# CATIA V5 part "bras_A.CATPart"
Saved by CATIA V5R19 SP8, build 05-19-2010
Part number: bras_A
Bounding box of the stored display mesh (mm): x -17.5 to 17.5, y -17.5 to 20.5, z 0 to 317.322
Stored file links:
  G:\EU_thinkMotion\CFAO_2010\MMS_groupe3\MMS_groupe3\A reprendre\mmugnier\Systeme_Cric_Y\Systeme_Cric_Y\bras_A.CATPart
  C:\Users\matthieu\Desktop\CFAO\Systeme_Cric_Y\Cric_Y.CATProduct
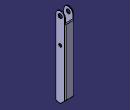
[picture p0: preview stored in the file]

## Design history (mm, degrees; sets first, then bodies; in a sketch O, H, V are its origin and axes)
Set1
  Plane1 "Plan de symétrie": linked copy from another document
  Plane2 "Plan exter bas": linked copy from another document
  Plane3: linked copy from another document
  Plane4 "Plan inter bas": linked copy from another document
  Line1 "Axe 3": linked copy from another document
  Plane5: linked copy from another document
  Plane6 "Plan exter droit": linked copy from another document
  Plane7 "Plan exter gauche": linked copy from another document
  Line2 "Axe 2": linked copy from another document
Body1 (main body)
  Sketch1 on Plane1, origin (0, 0, 0), H (0, 1, 0), V (0, 0, 1)
    line L1 (0, 0) -> (20.5, 20.5)
    line L2 (20.5, 20.5) -> (20.5, 279.5)
    line L3 (20.5, 279.5) -> (17.5, 282.5)
    line L4 (17.5, 282.5) -> (17.5, 300)
    arc A1 centre (0, 300) radius 17.5 from (17.5, 300) to (-17.5, 300) ccw
    point P5 (0, 300)
    line L5 (-17.5, 300) -> (-17.5, 4.6891)
    line L6 (-17.5, 4.6891) -> (0, 0)
    reference intersected line E1 through (20.5, 0) direction (0, 1) from Plane2
    reference intersected line E2 through (-17.5, 0) direction (0, 1) from Plane3
    reference intersected line E3 through (17.5, 0) direction (0, 1) from Plane4
    reference projected point E4 (0, 300) from Line1
    reference projected point E5 (0, 300) from Line1
    angle L3 L4 = 45
    angle L1 L6 = 120
    angle L1 L2 = 135
    vertical: L2 V, L4 V
    tangency: A1 L4, L5 A1
    coincidence: L2 E1, E2 L5, E3 L4, L3 E4, P5 E5
  Sketch2 on Plane5, origin (0, 0, 0), H (1, 0, 0), V (0, 1, 0)
    line L1 (-17.5, -17.5) -> (-14.5, -17.5)
    line L2 (17.5, -17.5) -> (17.5, 17.5)
    arc A1 centre (14.5, 17.5) radius 3 from (17.5, 17.5) to (14.5, 20.5) ccw
    line L3 (14.5, 20.5) -> (-14.5, 20.5)
    arc A2 centre (-14.5, 17.5) radius 3 from (-14.5, 20.5) to (-17.5, 17.5) ccw
    line L4 (-17.5, 17.5) -> (-17.5, -17.5)
    point P9 (14.5, -17.5)
    line L5 (14.5, -17.5) -> (14.5, 17.5)
    line L6 (14.5, 17.5) -> (-14.5, 17.5)
    line L7 (-14.5, 17.5) -> (-14.5, -17.5)
    line L8 (14.5, -17.5) -> (17.5, -17.5)
    reference intersected line E1 through (0, 17.5) direction (-1, 0) from Plane4
    reference intersected line E2 through (0, 20.5) direction (-1, 0) from Plane2
    reference intersected line E3 through (-17.5, 0) direction (0, 1) from Plane6
    reference intersected line E4 through (17.5, 0) direction (0, 1) from Plane7
    reference intersected line E5 through (0, -17.5) direction (-1, 0) from Plane3
    horizontal: L1 H, L8 H
    vertical: L2 V, L5 V, L7 V
    tangency: A1 L2, L3 A1, A2 L3, L4 A2
    coincidence: P9 L1, L1 L8, L6 E1, L3 E2, L4 E3, L2 E4, L8 E5
  SolidCombine1: FirstComponentProfile Sketch2, FirstComponentDirection Sketch2, SecondComponentProfile Sketch1, SecondComponentDirection Sketch1
  Sketch3 on Plane1, origin (0, 0, 0), H (0, 1, 0), V (0, 0, 1)
    circle A1 centre (0, 200) radius 6
    point P1 (0, 200)
    circle A2 centre (0, 300) radius 8
    point P2 (0, 300)
    reference projected point E1 (0, 300) from Line1
    reference projected point E2 (0, 200) from Line2
    radius A1 = 6
    radius A2 = 8
    coincidence: P2 E1, P1 E2
  Pocket1: profile Sketch3, direction (-1, 0, 0), through (limit type 3), opposite side through (limit type 3)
